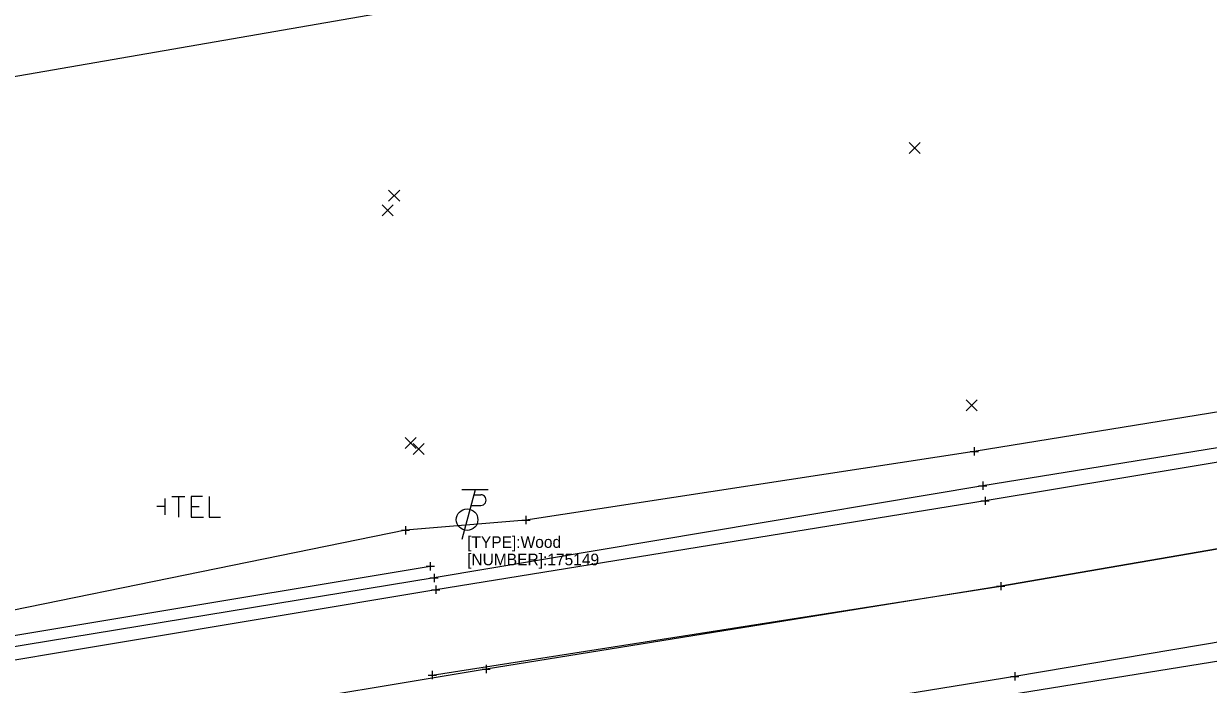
# Model space of a CAD drawing. Extents: x 1386013 to 1389776, y 604170 to 607009.
# Drawn here: x 1386419.5 to 1386562.3, y 604653.1 to 604732.7 of the extents above; entities that cross this region are included whole.
import ezdxf

# ---------------------------------------------------------------- set-up
doc = ezdxf.new("R2010")
doc.units = 0
for name, color, linetype in [('DV_X_Text', 7, 'Continuous'), ('PM_X_CL_Double_Solid', 7, 'Continuous'), ('PV_X_COP', 7, 'Continuous'), ('PV_X_EOP', 7, 'Continuous'), ('PV_X_Shoulder', 7, 'Continuous'), ('SH_Cut_Line', 7, 'Continuous'), ('SV_P_Mon_Cells_Set', 7, 'Continuous'), ('SV_X_Random_Point', 7, 'Continuous'), ('SV_X_Text', 7, 'Continuous'), ('SV_X_Toe_of_Slope', 7, 'Continuous'), ('SV_X_Top_of_Bank', 7, 'Continuous'), ('UT_X_Telecom_Cells', 7, 'Continuous')]:
    doc.layers.add(name, color=color, linetype=linetype)

msp = doc.modelspace()

# ---------------------------------------------------------------- linework, layer by layer
at = {"layer": 'DV_X_Text'}
for p, q in [((1386533.6, 604681.18), (1386534.6, 604681.18)), ((1386534.1, 604681.68), (1386534.1, 604680.68)), ((1386534.1, 604681.18), (1386534.1, 604681.18)), ((1386534.63, 604677.03), (1386535.63, 604677.03)), ((1386535.13, 604677.53), (1386535.13, 604676.53)), ((1386535.13, 604677.03), (1386535.13, 604677.03)), ((1386534.91, 604675.21), (1386535.91, 604675.21)), ((1386535.41, 604675.71), (1386535.41, 604674.71)), ((1386535.41, 604675.21), (1386535.41, 604675.21)), ((1386480.03, 604673.39), (1386480.03, 604672.39)), ((1386465.51, 604672.16), (1386465.51, 604671.16)), ((1386479.53, 604672.89), (1386480.53, 604672.89)), ((1386480.03, 604672.89), (1386480.03, 604672.89)), ((1386465.01, 604671.66), (1386466.01, 604671.66)), ((1386465.51, 604671.66), (1386465.51, 604671.66)), ((1386468.5, 604667.83), (1386468.5, 604666.83)), ((1386468, 604667.33), (1386469, 604667.33)), ((1386468.5, 604667.33), (1386468.5, 604667.33)), ((1386468.95, 604666.42), (1386468.95, 604665.42)), ((1386468.45, 604665.92), (1386469.45, 604665.92)), ((1386468.95, 604665.92), (1386468.95, 604665.92)), ((1386469.16, 604665), (1386469.16, 604664)), ((1386536.8, 604664.92), (1386537.8, 604664.92)), ((1386537.3, 604665.42), (1386537.3, 604664.42)), ((1386537.3, 604664.92), (1386537.3, 604664.92)), ((1386468.66, 604664.5), (1386469.66, 604664.5)), ((1386469.16, 604664.5), (1386469.16, 604664.5)), ((1386474.74, 604654.93), (1386475.74, 604654.93)), ((1386475.24, 604655.43), (1386475.24, 604654.43)), ((1386475.24, 604654.93), (1386475.24, 604654.93)), ((1386468.23, 604654.2), (1386469.23, 604654.2)), ((1386468.73, 604654.7), (1386468.73, 604653.7)), ((1386468.73, 604654.2), (1386468.73, 604654.2)), ((1386538.48, 604654.04), (1386539.48, 604654.04)), ((1386538.98, 604654.54), (1386538.98, 604653.54)), ((1386538.98, 604654.04), (1386538.98, 604654.04))]:
    msp.add_line(p, q, dxfattribs=at)
at = {"layer": 'PM_X_CL_Double_Solid'}
msp.add_lwpolyline([(1386468.73, 604654.2), (1386537.3, 604664.92), (1386594.48, 604674.79), (1386656.33, 604684.46), (1386713.85, 604693.61), (1386771.72, 604702.67), (1386828.75, 604712.1), (1386886.1, 604721.12), (1386941.92, 604730.57), (1387000.37, 604739.9)], dxfattribs=at)
at = {"layer": 'PV_X_COP'}
msp.add_lwpolyline([(1387000.37, 604739.9), (1386941.92, 604730.57), (1386886.1, 604721.12), (1386828.75, 604712.1), (1386771.72, 604702.67), (1386713.85, 604693.61), (1386656.33, 604684.46), (1386594.48, 604674.79), (1386537.3, 604664.92), (1386475.24, 604654.93), (1386414.35, 604644.79), (1386366.58, 604636.8), (1386295.22, 604625.24), (1386269.2, 604620.76)], dxfattribs=at)
at = {"layer": 'PV_X_EOP'}
for points in [[(1386999.09, 604750.97), (1386941.41, 604741.04), (1386884.67, 604731.59), (1386826.82, 604722.39), (1386770.2, 604713.13), (1386713.15, 604704.01), (1386654.93, 604694.71), (1386593.34, 604684.8), (1386535.41, 604675.21), (1386469.16, 604664.5), (1386392.09, 604651.62), (1386332.26, 604641.82), (1386267.39, 604631.1)], [(1387002.9, 604729.17), (1386943.42, 604719.4), (1386887.14, 604710.13), (1386830.12, 604700.78), (1386772.1, 604691.69), (1386715.3, 604682.94), (1386657.65, 604673.44), (1386596.41, 604663.71), (1386538.98, 604654.04), (1386477.51, 604644.07), (1386414.44, 604633.64), (1386368.83, 604626.04), (1386296.84, 604614.17), (1386270.69, 604609.87)]]:
    msp.add_lwpolyline(points, dxfattribs=at)
at = {"layer": 'PV_X_Shoulder'}
for points in [[(1386998.59, 604752.7), (1386940.97, 604743.32), (1386884.65, 604733.55), (1386826.54, 604724.64), (1386769.98, 604715.15), (1386712.42, 604706.07), (1386654.65, 604697.02), (1386593.22, 604686.44), (1386535.13, 604677.03), (1386468.95, 604665.92), (1386392.3, 604653.36), (1386331.76, 604643.52), (1386267.19, 604632.89)], [(1386985.4, 604722.84), (1386965.11, 604719.46), (1386961.9, 604720.55), (1386943.38, 604718.17), (1386887.62, 604708.36), (1386830.36, 604699.21), (1386772.3, 604689.74), (1386715.56, 604681.18), (1386657.89, 604671.95), (1386596.66, 604661.6), (1386577.12, 604657.52), (1386569.07, 604656.76), (1386539.67, 604652.01), (1386479.08, 604642.34), (1386478.07, 604642.14), (1386414.53, 604632.43), (1386369.38, 604624.9), (1386296.82, 604613.19), (1386270.73, 604608.85)]]:
    msp.add_lwpolyline(points, dxfattribs=at)
at = {"layer": 'SH_Cut_Line'}
msp.add_lwpolyline([(1386387.56, 604497.79), (1386350, 604714.56), (1386685.02, 604772.59), (1386722.57, 604555.82)], close=True, dxfattribs=at)
at = {"layer": 'SV_P_Mon_Cells_Set'}
for p, q in [((1386473.9, 604676.54), (1386472.29, 604670.54)), ((1386475.5, 604676.54), (1386472.3, 604676.54)), ((1386473.74, 604675.94), (1386474.59, 604675.94)), ((1386473.4, 604674.66), (1386474.59, 604674.66))]:
    msp.add_line(p, q, dxfattribs=at)
msp.add_circle((1386472.94, 604672.94), 1.3, dxfattribs=at)
msp.add_arc((1386474.6, 604675.3), 0.638, 268.8767, 91.1233, dxfattribs=at)
at = {"layer": 'SV_X_Random_Point'}
for p, q in [((1386526.26, 604717.08), (1386527.59, 604718.41)), ((1386526.26, 604718.41), (1386527.59, 604717.08)), ((1386463.48, 604711.35), (1386464.81, 604712.68)), ((1386463.48, 604712.68), (1386464.81, 604711.35)), ((1386462.71, 604709.56), (1386464.04, 604710.9)), ((1386462.71, 604710.9), (1386464.04, 604709.56)), ((1386533.14, 604686.07), (1386534.47, 604687.41)), ((1386533.14, 604687.41), (1386534.47, 604686.07)), ((1386465.47, 604681.53), (1386466.81, 604682.86)), ((1386465.47, 604682.86), (1386466.81, 604681.53)), ((1386466.45, 604680.79), (1386467.78, 604682.13)), ((1386466.45, 604682.13), (1386467.78, 604680.79))]:
    msp.add_line(p, q, dxfattribs=at)
at = {"layer": 'SV_X_Toe_of_Slope'}
msp.add_lwpolyline([(1387571.9, 604860.13), (1387513.17, 604847.9), (1387455.73, 604837.69), (1387401.04, 604827.65), (1387339.29, 604815.83), (1387289.1, 604807.74), (1387230.03, 604798.15), (1387173.08, 604787.71), (1387123.84, 604780.19), (1387058.58, 604768.72), (1386997.09, 604757.11), (1386939.93, 604748.73), (1386883.98, 604739), (1386826.09, 604728.82), (1386769.04, 604719.03), (1386711.7, 604710.77), (1386654.03, 604700.72), (1386592.6, 604690.63), (1386534.1, 604681.18), (1386480.03, 604672.89), (1386465.51, 604671.66), (1386391.46, 604656.56), (1386330.8, 604647.36), (1386266.18, 604637.16)], dxfattribs=at)
at = {"layer": 'SV_X_Top_of_Bank'}
msp.add_lwpolyline([(1386266.95, 604634.29), (1386331.82, 604644.7), (1386392.38, 604654.68), (1386468.5, 604667.33)], dxfattribs=at)
at = {"layer": 'UT_X_Telecom_Cells'}
for p, q in [((1386436.52, 604673.51), (1386436.52, 604675.51)), ((1386436.52, 604674.51), (1386435.52, 604674.51))]:
    msp.add_line(p, q, dxfattribs=at)
for points in [[(1386437.33, 604675.75), (1386438.89, 604675.75)], [(1386438.12, 604675.75), (1386438.12, 604673.25)], [(1386441.03, 604675.75), (1386439.67, 604675.75), (1386439.67, 604673.25), (1386441.13, 604673.25)], [(1386441.82, 604675.75), (1386441.82, 604673.25), (1386443.18, 604673.25)], [(1386439.67, 604674.51), (1386440.64, 604674.51)]]:
    msp.add_lwpolyline(points, dxfattribs=at)

# ---------------------------------------------------------------- texts
at = {"layer": 'SV_X_Text'}
for s, p in [('[TYPE]:Wood', (1386472.94, 604669.54)), ('[NUMBER]:175149', (1386472.94, 604667.44))]:
    msp.add_text(s, height=1.4, dxfattribs=at).set_placement(p)

doc.saveas('drawing.dxf')
